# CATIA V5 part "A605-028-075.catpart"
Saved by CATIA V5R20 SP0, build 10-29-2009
Part number: A605-028-075
Source: Unknown
Property "A": "0.000"
Property "ARTICLENO": "A605-028-075"
Property "BOMINFO": "A605-028-075"
Property "CODE": "A605-028-075"
Property "D": "9.000"
Property "FORM": "A"
Property "L": "75.000"
Property "L1": "45.000"
Property "LINA": "A605-028-075"
Property "NB": "A605-028-075"
Property "NBSYN": "$CODE."
Property "NN": "A605"
Property "NT": "Wear Plates, self-lubricating"
Property "SCREW": "2*M8X10"
Property "SUPPLIER": "CF"
Property "W": "28.000"
Bounding box of the stored display mesh (mm): x -28 to 0, y 0 to 5, z -75 to 0
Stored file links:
  C:\Users\Utente\Desktop\3D files A605\A605-028-075.catpart
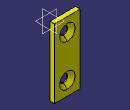
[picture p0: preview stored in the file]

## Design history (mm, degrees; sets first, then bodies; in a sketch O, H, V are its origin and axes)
Body1 "Geometry.1" (main body)
  Solid1 "A605-028-075.catpart": solid without history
